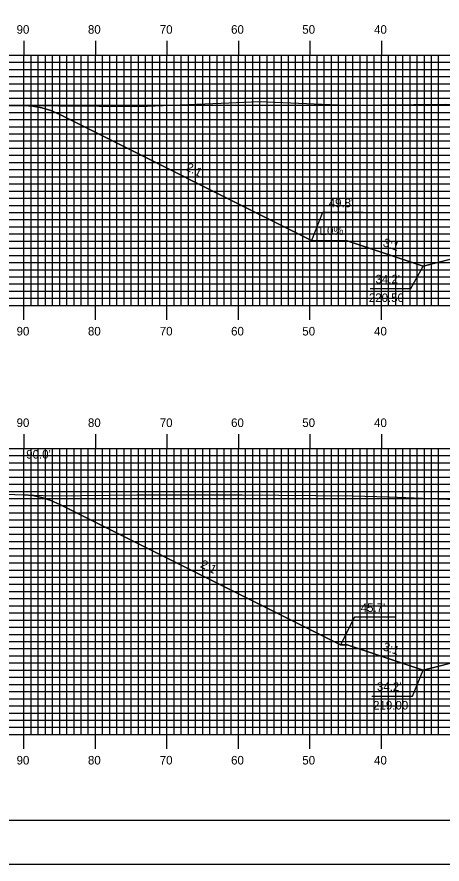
# Model space of a CAD drawing. Extents: x 1816883 to 1817226, y 442591 to 442811.
# Drawn here: x 1816957.6 to 1817017.1, y 442590.5 to 442709 of the extents above; entities that cross this region are included whole.
import ezdxf

# ---------------------------------------------------------------- set-up
doc = ezdxf.new("R2010")
doc.units = 0
for name, color, linetype in [('ANNOTATION', 7, 'Continuous'), ('BORDER', 7, 'Continuous'), ('D_Roadway_Centerline', 7, 'Continuous'), ('D_Roadway_SlopeLines', 7, 'Continuous'), ('D_Text_Standard', 7, 'Continuous'), ('H_V ANNOTATION', 7, 'Continuous'), ('MAJOR', 7, 'Continuous'), ('MINOR', 7, 'Continuous'), ('PLOT BOUNDARY', 7, 'Continuous'), ('S_Roadway_Centerline', 7, 'Continuous')]:
    doc.layers.add(name, color=color, linetype=linetype)

msp = doc.modelspace()

# ---------------------------------------------------------------- linework, layer by layer
at = {"layer": 'ANNOTATION'}
for points in [[(1817006.04, 442681.69), (1817000.35, 442681.69), (1816998.81, 442677.76)], [(1817007.01, 442671.03), (1817012.71, 442671.03), (1817014.41, 442674.17)], [(1817010.52, 442625.07), (1817004.83, 442625.07), (1817002.86, 442621.22)], [(1817007.23, 442614.03), (1817012.92, 442614.03), (1817014.41, 442617.67)]]:
    msp.add_lwpolyline(points, dxfattribs=at)
at = {"layer": 'BORDER'}
msp.add_lwpolyline([(1816898.99, 442596.67), (1817218.99, 442596.67), (1817218.99, 442806.67), (1816898.99, 442806.67)], close=True, dxfattribs=at)
at = {"layer": 'D_Roadway_Centerline'}
for points in [[(1816958.59, 442696.64), (1816959.84, 442696.56), (1816961.09, 442696.31), (1816962.34, 442695.92), (1816963.59, 442695.37), (1816998.81, 442677.76), (1817003.78, 442677.71), (1817014.41, 442674.17), (1817018.41, 442675.17), (1817028.59, 442677.71), (1817036.59, 442678.03), (1817048.59, 442678.27), (1817060.59, 442678.03), (1817068.59, 442677.71), (1817078.76, 442675.17), (1817082.76, 442674.17), (1817093.39, 442677.71), (1817101.65, 442677.79), (1817133.59, 442693.76), (1817134.84, 442694.3), (1817136.09, 442694.68), (1817137.34, 442694.88), (1817138.59, 442694.92)], [(1816958.59, 442642.2), (1816959.84, 442642.08), (1816961.09, 442641.81), (1816962.34, 442641.41), (1816963.59, 442640.85), (1817002.86, 442621.22), (1817003.78, 442621.21), (1817014.41, 442617.67), (1817018.41, 442618.67), (1817028.59, 442621.21), (1817036.59, 442621.53), (1817048.59, 442621.77), (1817060.59, 442621.53), (1817068.59, 442621.21), (1817078.76, 442618.67), (1817082.76, 442617.67), (1817093.39, 442621.21), (1817102.53, 442621.3), (1817133.59, 442636.83), (1817134.84, 442637.37), (1817136.09, 442637.72), (1817137.34, 442637.9), (1817138.59, 442637.9)]]:
    msp.add_lwpolyline(points, dxfattribs=at)
at = {"layer": 'D_Roadway_SlopeLines'}
for points in [[(1817003.78, 442677.71), (1816998.81, 442677.76), (1816963.59, 442695.37), (1816962.34, 442695.92), (1816961.09, 442696.31), (1816959.84, 442696.56), (1816958.59, 442696.64)], [(1817014.41, 442674.17), (1817003.78, 442677.71)], [(1817028.59, 442677.71), (1817014.41, 442674.17)], [(1817003.78, 442621.21), (1817002.86, 442621.22), (1816963.59, 442640.85), (1816962.34, 442641.41), (1816961.09, 442641.81), (1816959.84, 442642.08), (1816958.59, 442642.2)], [(1817014.41, 442617.67), (1817003.78, 442621.21)], [(1817028.59, 442621.21), (1817014.41, 442617.67)]]:
    msp.add_lwpolyline(points, dxfattribs=at)
at = {"layer": 'MAJOR'}
for p, q in [((1816958.59, 442705.67), (1816958.59, 442703.67)), ((1816968.59, 442705.67), (1816968.59, 442703.67)), ((1816978.59, 442705.67), (1816978.59, 442703.67)), ((1816988.59, 442705.67), (1816988.59, 442703.67)), ((1816998.59, 442705.67), (1816998.59, 442703.67)), ((1817008.59, 442705.67), (1817008.59, 442703.67)), ((1816908.59, 442703.67), (1817188.59, 442703.67)), ((1816908.59, 442703.67), (1817188.59, 442703.67)), ((1816958.59, 442668.67), (1816958.59, 442703.67)), ((1816968.59, 442668.67), (1816968.59, 442703.67)), ((1816978.59, 442668.67), (1816978.59, 442703.67)), ((1816988.59, 442668.67), (1816988.59, 442703.67)), ((1816998.59, 442668.67), (1816998.59, 442703.67)), ((1817008.59, 442668.67), (1817008.59, 442703.67)), ((1816908.59, 442698.67), (1817188.59, 442698.67)), ((1816908.59, 442693.67), (1817188.59, 442693.67)), ((1816908.59, 442688.67), (1817188.59, 442688.67)), ((1816908.59, 442683.67), (1817188.59, 442683.67)), ((1816908.59, 442678.67), (1817188.59, 442678.67)), ((1816908.59, 442673.67), (1817188.59, 442673.67)), ((1816908.59, 442668.67), (1817188.59, 442668.67)), ((1816908.59, 442668.67), (1817188.59, 442668.67)), ((1816958.59, 442666.66), (1816958.59, 442668.67)), ((1816968.59, 442666.66), (1816968.59, 442668.67)), ((1816978.59, 442666.66), (1816978.59, 442668.67)), ((1816988.59, 442666.66), (1816988.59, 442668.67)), ((1816998.59, 442666.66), (1816998.59, 442668.67)), ((1817008.59, 442666.66), (1817008.59, 442668.67)), ((1816958.59, 442650.67), (1816958.59, 442648.67)), ((1816968.59, 442650.67), (1816968.59, 442648.67)), ((1816978.59, 442650.67), (1816978.59, 442648.67)), ((1816988.59, 442650.67), (1816988.59, 442648.67)), ((1816998.59, 442650.67), (1816998.59, 442648.67)), ((1817008.59, 442650.67), (1817008.59, 442648.67)), ((1816908.59, 442648.67), (1817188.59, 442648.67)), ((1816908.59, 442648.67), (1817188.59, 442648.67)), ((1816958.59, 442608.67), (1816958.59, 442648.67)), ((1816968.59, 442608.67), (1816968.59, 442648.67)), ((1816978.59, 442608.67), (1816978.59, 442648.67)), ((1816988.59, 442608.67), (1816988.59, 442648.67)), ((1816998.59, 442608.67), (1816998.59, 442648.67)), ((1817008.59, 442608.67), (1817008.59, 442648.67)), ((1816908.59, 442643.67), (1817188.59, 442643.67)), ((1816908.59, 442638.67), (1817188.59, 442638.67)), ((1816908.59, 442633.67), (1817188.59, 442633.67)), ((1816908.59, 442628.67), (1817188.59, 442628.67)), ((1816908.59, 442623.67), (1817188.59, 442623.67)), ((1816908.59, 442618.67), (1817188.59, 442618.67)), ((1816908.59, 442613.67), (1817188.59, 442613.67)), ((1816908.59, 442608.67), (1817188.59, 442608.67)), ((1816908.59, 442608.67), (1817188.59, 442608.67)), ((1816958.59, 442606.66), (1816958.59, 442608.67)), ((1816968.59, 442606.66), (1816968.59, 442608.67)), ((1816978.59, 442606.66), (1816978.59, 442608.67)), ((1816988.59, 442606.66), (1816988.59, 442608.67)), ((1816998.59, 442606.66), (1816998.59, 442608.67)), ((1817008.59, 442606.66), (1817008.59, 442608.67))]:
    msp.add_line(p, q, dxfattribs=at)
at = {"layer": 'MINOR'}
for p, q in [((1816959.59, 442668.67), (1816959.59, 442703.67)), ((1816960.59, 442668.67), (1816960.59, 442703.67)), ((1816961.59, 442668.67), (1816961.59, 442703.67)), ((1816962.59, 442668.67), (1816962.59, 442703.67)), ((1816963.59, 442668.67), (1816963.59, 442703.67)), ((1816964.59, 442668.67), (1816964.59, 442703.67)), ((1816965.59, 442668.67), (1816965.59, 442703.67)), ((1816966.59, 442668.67), (1816966.59, 442703.67)), ((1816967.59, 442668.67), (1816967.59, 442703.67)), ((1816969.59, 442668.67), (1816969.59, 442703.67)), ((1816970.59, 442668.67), (1816970.59, 442703.67)), ((1816971.59, 442668.67), (1816971.59, 442703.67)), ((1816972.59, 442668.67), (1816972.59, 442703.67)), ((1816973.59, 442668.67), (1816973.59, 442703.67)), ((1816974.59, 442668.67), (1816974.59, 442703.67)), ((1816975.59, 442668.67), (1816975.59, 442703.67)), ((1816976.59, 442668.67), (1816976.59, 442703.67)), ((1816977.59, 442668.67), (1816977.59, 442703.67)), ((1816979.59, 442668.67), (1816979.59, 442703.67)), ((1816980.59, 442668.67), (1816980.59, 442703.67)), ((1816981.59, 442668.67), (1816981.59, 442703.67)), ((1816982.59, 442668.67), (1816982.59, 442703.67)), ((1816983.59, 442668.67), (1816983.59, 442703.67)), ((1816984.59, 442668.67), (1816984.59, 442703.67)), ((1816985.59, 442668.67), (1816985.59, 442703.67)), ((1816986.59, 442668.67), (1816986.59, 442703.67)), ((1816987.59, 442668.67), (1816987.59, 442703.67)), ((1816989.59, 442668.67), (1816989.59, 442703.67)), ((1816990.59, 442668.67), (1816990.59, 442703.67)), ((1816991.59, 442668.67), (1816991.59, 442703.67)), ((1816992.59, 442668.67), (1816992.59, 442703.67)), ((1816993.59, 442668.67), (1816993.59, 442703.67)), ((1816994.59, 442668.67), (1816994.59, 442703.67)), ((1816995.59, 442668.67), (1816995.59, 442703.67)), ((1816996.59, 442668.67), (1816996.59, 442703.67)), ((1816997.59, 442668.67), (1816997.59, 442703.67)), ((1816999.59, 442668.67), (1816999.59, 442703.67)), ((1817000.59, 442668.67), (1817000.59, 442703.67)), ((1817001.59, 442668.67), (1817001.59, 442703.67)), ((1817002.59, 442668.67), (1817002.59, 442703.67)), ((1817003.59, 442668.67), (1817003.59, 442703.67)), ((1817004.59, 442668.67), (1817004.59, 442703.67)), ((1817005.59, 442668.67), (1817005.59, 442703.67)), ((1817006.59, 442668.67), (1817006.59, 442703.67)), ((1817007.59, 442668.67), (1817007.59, 442703.67)), ((1817009.59, 442668.67), (1817009.59, 442703.67)), ((1817010.59, 442668.67), (1817010.59, 442703.67)), ((1817011.59, 442668.67), (1817011.59, 442703.67)), ((1817012.59, 442668.67), (1817012.59, 442703.67)), ((1817013.59, 442668.67), (1817013.59, 442703.67)), ((1817014.59, 442668.67), (1817014.59, 442703.67)), ((1817015.59, 442668.67), (1817015.59, 442703.67)), ((1817016.59, 442668.67), (1817016.59, 442703.67)), ((1816908.59, 442702.67), (1817188.59, 442702.67)), ((1816908.59, 442701.67), (1817188.59, 442701.67)), ((1816908.59, 442700.67), (1817188.59, 442700.67)), ((1816908.59, 442699.67), (1817188.59, 442699.67)), ((1816908.59, 442697.67), (1817188.59, 442697.67)), ((1816908.59, 442696.67), (1817188.59, 442696.67)), ((1816908.59, 442695.67), (1817188.59, 442695.67)), ((1816908.59, 442694.67), (1817188.59, 442694.67)), ((1816908.59, 442692.67), (1817188.59, 442692.67)), ((1816908.59, 442691.67), (1817188.59, 442691.67)), ((1816908.59, 442690.67), (1817188.59, 442690.67)), ((1816908.59, 442689.67), (1817188.59, 442689.67)), ((1816908.59, 442687.67), (1817188.59, 442687.67)), ((1816908.59, 442686.67), (1817188.59, 442686.67)), ((1816908.59, 442685.67), (1817188.59, 442685.67)), ((1816908.59, 442684.67), (1817188.59, 442684.67)), ((1816908.59, 442682.67), (1817188.59, 442682.67)), ((1816908.59, 442681.67), (1817188.59, 442681.67)), ((1816908.59, 442680.67), (1817188.59, 442680.67)), ((1816908.59, 442679.67), (1817188.59, 442679.67)), ((1816908.59, 442677.67), (1817188.59, 442677.67)), ((1816908.59, 442676.67), (1817188.59, 442676.67)), ((1816908.59, 442675.67), (1817188.59, 442675.67)), ((1816908.59, 442674.67), (1817188.59, 442674.67)), ((1816908.59, 442672.67), (1817188.59, 442672.67)), ((1816908.59, 442671.67), (1817188.59, 442671.67)), ((1816908.59, 442670.67), (1817188.59, 442670.67)), ((1816908.59, 442669.67), (1817188.59, 442669.67)), ((1816908.59, 442647.67), (1817188.59, 442647.67)), ((1816959.59, 442608.67), (1816959.59, 442648.67)), ((1816960.59, 442608.67), (1816960.59, 442648.67)), ((1816961.59, 442608.67), (1816961.59, 442648.67)), ((1816962.59, 442608.67), (1816962.59, 442648.67)), ((1816963.59, 442608.67), (1816963.59, 442648.67)), ((1816964.59, 442608.67), (1816964.59, 442648.67)), ((1816965.59, 442608.67), (1816965.59, 442648.67)), ((1816966.59, 442608.67), (1816966.59, 442648.67)), ((1816967.59, 442608.67), (1816967.59, 442648.67)), ((1816969.59, 442608.67), (1816969.59, 442648.67)), ((1816970.59, 442608.67), (1816970.59, 442648.67)), ((1816971.59, 442608.67), (1816971.59, 442648.67)), ((1816972.59, 442608.67), (1816972.59, 442648.67)), ((1816973.59, 442608.67), (1816973.59, 442648.67)), ((1816974.59, 442608.67), (1816974.59, 442648.67)), ((1816975.59, 442608.67), (1816975.59, 442648.67)), ((1816976.59, 442608.67), (1816976.59, 442648.67)), ((1816977.59, 442608.67), (1816977.59, 442648.67)), ((1816979.59, 442608.67), (1816979.59, 442648.67)), ((1816980.59, 442608.67), (1816980.59, 442648.67)), ((1816981.59, 442608.67), (1816981.59, 442648.67)), ((1816982.59, 442608.67), (1816982.59, 442648.67)), ((1816983.59, 442608.67), (1816983.59, 442648.67)), ((1816984.59, 442608.67), (1816984.59, 442648.67)), ((1816985.59, 442608.67), (1816985.59, 442648.67)), ((1816986.59, 442608.67), (1816986.59, 442648.67)), ((1816987.59, 442608.67), (1816987.59, 442648.67)), ((1816989.59, 442608.67), (1816989.59, 442648.67)), ((1816990.59, 442608.67), (1816990.59, 442648.67)), ((1816991.59, 442608.67), (1816991.59, 442648.67)), ((1816992.59, 442608.67), (1816992.59, 442648.67)), ((1816993.59, 442608.67), (1816993.59, 442648.67)), ((1816994.59, 442608.67), (1816994.59, 442648.67)), ((1816995.59, 442608.67), (1816995.59, 442648.67)), ((1816996.59, 442608.67), (1816996.59, 442648.67)), ((1816997.59, 442608.67), (1816997.59, 442648.67)), ((1816999.59, 442608.67), (1816999.59, 442648.67)), ((1817000.59, 442608.67), (1817000.59, 442648.67)), ((1817001.59, 442608.67), (1817001.59, 442648.67)), ((1817002.59, 442608.67), (1817002.59, 442648.67)), ((1817003.59, 442608.67), (1817003.59, 442648.67)), ((1817004.59, 442608.67), (1817004.59, 442648.67)), ((1817005.59, 442608.67), (1817005.59, 442648.67)), ((1817006.59, 442608.67), (1817006.59, 442648.67)), ((1817007.59, 442608.67), (1817007.59, 442648.67)), ((1817009.59, 442608.67), (1817009.59, 442648.67)), ((1817010.59, 442608.67), (1817010.59, 442648.67)), ((1817011.59, 442608.67), (1817011.59, 442648.67)), ((1817012.59, 442608.67), (1817012.59, 442648.67)), ((1817013.59, 442608.67), (1817013.59, 442648.67)), ((1817014.59, 442608.67), (1817014.59, 442648.67)), ((1817015.59, 442608.67), (1817015.59, 442648.67)), ((1817016.59, 442608.67), (1817016.59, 442648.67)), ((1816908.59, 442646.67), (1817188.59, 442646.67)), ((1816908.59, 442645.67), (1817188.59, 442645.67)), ((1816908.59, 442644.67), (1817188.59, 442644.67)), ((1816908.59, 442642.67), (1817188.59, 442642.67)), ((1816908.59, 442641.67), (1817188.59, 442641.67)), ((1816908.59, 442640.67), (1817188.59, 442640.67)), ((1816908.59, 442639.67), (1817188.59, 442639.67)), ((1816908.59, 442637.67), (1817188.59, 442637.67)), ((1816908.59, 442636.67), (1817188.59, 442636.67)), ((1816908.59, 442635.67), (1817188.59, 442635.67)), ((1816908.59, 442634.67), (1817188.59, 442634.67)), ((1816908.59, 442632.67), (1817188.59, 442632.67)), ((1816908.59, 442631.67), (1817188.59, 442631.67)), ((1816908.59, 442630.67), (1817188.59, 442630.67)), ((1816908.59, 442629.67), (1817188.59, 442629.67)), ((1816908.59, 442627.67), (1817188.59, 442627.67)), ((1816908.59, 442626.67), (1817188.59, 442626.67)), ((1816908.59, 442625.67), (1817188.59, 442625.67)), ((1816908.59, 442624.67), (1817188.59, 442624.67)), ((1816908.59, 442622.67), (1817188.59, 442622.67)), ((1816908.59, 442621.67), (1817188.59, 442621.67)), ((1816908.59, 442620.67), (1817188.59, 442620.67)), ((1816908.59, 442619.67), (1817188.59, 442619.67)), ((1816908.59, 442617.67), (1817188.59, 442617.67)), ((1816908.59, 442616.67), (1817188.59, 442616.67)), ((1816908.59, 442615.67), (1817188.59, 442615.67)), ((1816908.59, 442614.67), (1817188.59, 442614.67)), ((1816908.59, 442612.67), (1817188.59, 442612.67)), ((1816908.59, 442611.67), (1817188.59, 442611.67)), ((1816908.59, 442610.67), (1817188.59, 442610.67)), ((1816908.59, 442609.67), (1817188.59, 442609.67))]:
    msp.add_line(p, q, dxfattribs=at)
at = {"layer": 'PLOT BOUNDARY'}
msp.add_lwpolyline([(1816882.8, 442590.55), (1817222.8, 442590.55), (1817222.8, 442810.55), (1816882.8, 442810.55)], close=True, dxfattribs=at)
at = {"layer": 'S_Roadway_Centerline'}
for points in [[(1816945.61, 442696.57), (1816957.82, 442696.65), (1816963.42, 442696.6), (1816974.67, 442696.49), (1816986.19, 442696.98), (1816991.48, 442697.18), (1817003.59, 442696.66), (1817008.75, 442696.73), (1817017.48, 442696.83), (1817025.38, 442696.78), (1817031.42, 442696.85), (1817042.12, 442696.69), (1817044.01, 442696.7), (1817052.76, 442696.7), (1817058.07, 442696.71), (1817059.32, 442696.73), (1817061.28, 442696.69), (1817075.83, 442696.56), (1817084.59, 442696.39)], [(1816954.65, 442642.34), (1816962.57, 442642.05), (1816970.49, 442642.14), (1816974.39, 442642.2), (1816988.01, 442642.17), (1816988.23, 442642.17), (1816989.11, 442642.17), (1817004.56, 442642.05), (1817009.66, 442641.92), (1817021.34, 442641.44), (1817028.42, 442641.62), (1817037.57, 442641.09), (1817041.73, 442640.97), (1817055.84, 442640.66), (1817055.88, 442640.66), (1817056.03, 442640.66), (1817071.91, 442640.29), (1817081.78, 442639.98)]]:
    msp.add_lwpolyline(points, dxfattribs=at)

# ---------------------------------------------------------------- texts
at = {"layer": 'ANNOTATION'}
for s, rotation, p in [('2:1', 333.4349, (1816981.13, 442687.63)), ('1.0%', 359.4271, (1816999.63, 442678.55)), ('3:1', 341.5651, (1817008.7, 442676.98)), ('2:1', 333.4349, (1816983.16, 442632.1)), ('3:1', 341.5651, (1817008.7, 442620.48))]:
    msp.add_text(s, height=1.2, rotation=rotation, dxfattribs=at).set_placement(p)
for s, p in [("49.8'", (1817001.21, 442682.41)), ("34.2'", (1817007.75, 442671.75)), ('220.50', (1817006.83, 442669.15)), ("45.7'", (1817005.69, 442625.8)), ("34.2'", (1817007.96, 442614.76)), ('219.00', (1817007.43, 442612.16))]:
    msp.add_text(s, height=1.2, dxfattribs=at).set_placement(p)
at = {"layer": 'D_Text_Standard'}
msp.add_text("90.0'", height=1.2, dxfattribs=at).set_placement((1816958.91, 442647.25))
at = {"layer": 'H_V ANNOTATION'}
for s, p in [('90', (1816957.56, 442706.67)), ('80', (1816967.54, 442706.67)), ('70', (1816977.59, 442706.67)), ('60', (1816987.56, 442706.67)), ('50', (1816997.52, 442706.67)), ('40', (1817007.56, 442706.67)), ('90', (1816957.56, 442664.47)), ('80', (1816967.54, 442664.47)), ('70', (1816977.59, 442664.47)), ('60', (1816987.56, 442664.47)), ('50', (1816997.52, 442664.47)), ('40', (1817007.56, 442664.47)), ('90', (1816957.56, 442651.67)), ('80', (1816967.54, 442651.67)), ('70', (1816977.59, 442651.67)), ('60', (1816987.56, 442651.67)), ('50', (1816997.52, 442651.67)), ('40', (1817007.56, 442651.67)), ('90', (1816957.56, 442604.47)), ('80', (1816967.54, 442604.47)), ('70', (1816977.59, 442604.47)), ('60', (1816987.56, 442604.47)), ('50', (1816997.52, 442604.47)), ('40', (1817007.56, 442604.47))]:
    msp.add_text(s, height=1.2, dxfattribs=at).set_placement(p)

doc.saveas('drawing.dxf')
